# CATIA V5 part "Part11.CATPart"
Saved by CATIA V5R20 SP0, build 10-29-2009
Part number: 1DIN912625_DIN 912 M6 x 25 --- 25C
Revision: ANY
Definition: UNKNOWN
Nomenclature: 1DIN912625_DIN 912 M6 x 25 --- 25C
Source: Unknown
Bounding box of the stored display mesh (mm): x 0 to 31, y -5 to 5, z -5 to 5
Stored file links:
  C:\Users\Utente\Desktop\IO LAVORO\3D X SITO CF\CUMSA\3D files CG\CG 604035\Part11.CATPart
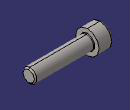
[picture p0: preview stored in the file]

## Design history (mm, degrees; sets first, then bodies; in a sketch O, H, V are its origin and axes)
Body1 "Hex" (main body)
  Solid1: solid without history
